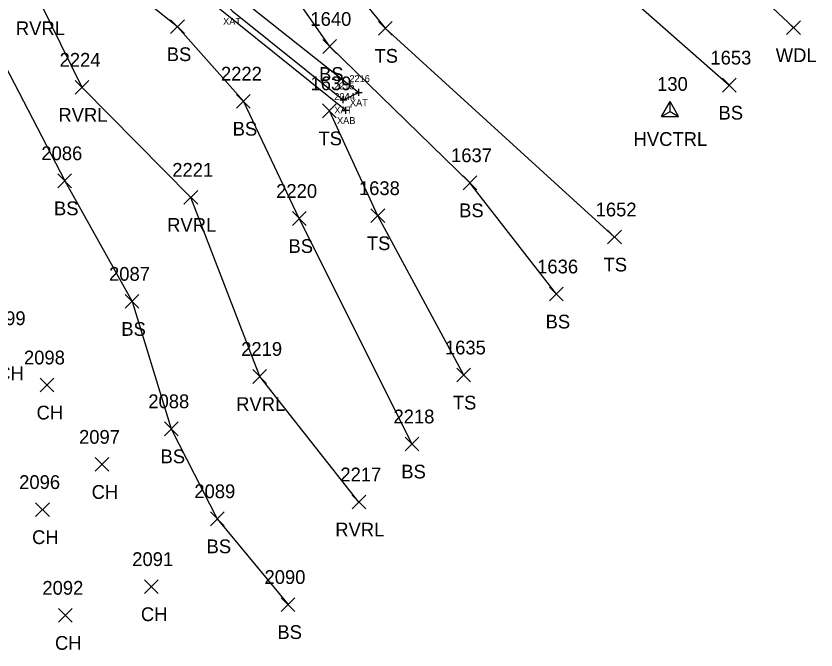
# Model space of a CAD drawing. Extents: x 1647133 to 1649138, y 411736 to 414924.
# Drawn here: x 1648998.1 to 1649114.4, y 412087.9 to 412180 of the extents above; entities that cross this region are included whole.
import ezdxf

# ---------------------------------------------------------------- set-up
doc = ezdxf.new("R2010")
doc.units = 0
for name, color, linetype in [('B_A', 7, 'Continuous'), ('B_I', 7, 'Continuous'), ('B_TIC', 7, 'Continuous'), ('BSUBM', 7, 'Continuous'), ('C_A', 7, 'Continuous'), ('C_I', 7, 'Continuous'), ('CPSM', 7, 'Continuous'), ('L_A', 7, 'Continuous'), ('L_I', 7, 'Continuous'), ('L_TIC', 7, 'Continuous'), ('LAWA', 7, 'Continuous'), ('LAWE', 7, 'Continuous'), ('LELB', 7, 'Continuous')]:
    doc.layers.add(name, color=color, linetype=linetype)

msp = doc.modelspace()

# ---------------------------------------------------------------- linework, layer by layer
at = {"layer": 'B_TIC'}
for p, q in [((1649047.93, 412168.89), (1649048, 412168.89)), ((1649047.93, 412168.89), (1649048, 412168.89)), ((1649045.66, 412167.83), (1649045.74, 412167.83)), ((1649046.03, 412166.3), (1649046.11, 412166.3))]:
    msp.add_line(p, q, dxfattribs=at)
for points in [[(1649047.42, 412168.89), (1649048.42, 412168.89)], [(1649047.42, 412168.89), (1649048.42, 412168.89)], [(1649047.92, 412168.39), (1649047.92, 412169.39)], [(1649047.92, 412168.39), (1649047.92, 412169.39)], [(1649045.16, 412167.83), (1649046.16, 412167.83)], [(1649045.66, 412167.33), (1649045.66, 412168.33)], [(1649045.53, 412166.3), (1649046.53, 412166.3)], [(1649046.03, 412165.8), (1649046.03, 412166.8)]]:
    msp.add_lwpolyline(points, dxfattribs=at)
at = {"layer": 'BSUBM'}
for points in [[(1648980.21, 412272.22), (1648969.68, 412271.32), (1648969.26, 412266.42), (1648968.93, 412254.38), (1648969.05, 412251.5), (1648969.53, 412251.26), (1648969.79, 412227.7), (1648987.09, 412207.48), (1648990.12, 412205.51), (1649004.16, 412198.22), (1649004.66, 412197.94), (1649016.35, 412193.1), (1649025.31, 412183.01), (1649046.03, 412166.3)], [(1648988.03, 412209.13), (1648991.51, 412213.01), (1648996.39, 412206.99), (1649003.26, 412202.8), (1649010.46, 412199.77), (1649020.04, 412194.1), (1649031.36, 412182.02), (1649047.92, 412168.89)], [(1648988.03, 412209.13), (1648994.26, 412203.89), (1649001.04, 412200.28), (1649007.86, 412197.37), (1649018.25, 412192.59), (1649029.49, 412180.72), (1649045.66, 412167.83), (1649047.92, 412168.89)]]:
    msp.add_lwpolyline(points, dxfattribs=at)
at = {"layer": 'CPSM'}
for p, q in [((1649091.92, 412165.4), (1649093.17, 412167.56)), ((1649094.42, 412165.4), (1649093.17, 412167.56)), ((1649093.17, 412166.12), (1649093.17, 412167.56)), ((1649091.92, 412165.4), (1649093.17, 412166.12)), ((1649091.92, 412165.4), (1649094.42, 412165.4)), ((1649093.17, 412166.12), (1649093.17, 412166.12)), ((1649093.17, 412166.12), (1649094.42, 412165.4))]:
    msp.add_line(p, q, dxfattribs=at)
at = {"layer": 'L_TIC'}
for points in [[(1649020.56, 412177.44), (1649022.56, 412179.44)], [(1649022.56, 412177.44), (1649020.56, 412179.44)], [(1649050.79, 412177.2), (1649052.79, 412179.2)], [(1649052.79, 412177.2), (1649050.79, 412179.2)], [(1649110.12, 412177.3), (1649112.12, 412179.3)], [(1649112.12, 412177.3), (1649110.12, 412179.3)], [(1649042.7, 412174.56), (1649044.7, 412176.56)], [(1649044.7, 412174.56), (1649042.7, 412176.56)], [(1649100.78, 412168.94), (1649102.78, 412170.94)], [(1649102.78, 412168.94), (1649100.78, 412170.94)], [(1649006.68, 412168.63), (1649008.68, 412170.63)], [(1649008.68, 412168.63), (1649006.68, 412170.63)], [(1649030.14, 412166.61), (1649032.14, 412168.61)], [(1649032.14, 412166.61), (1649030.14, 412168.61)], [(1649042.64, 412165.21), (1649044.64, 412167.21)], [(1649044.64, 412165.21), (1649042.64, 412167.21)], [(1649004.16, 412155.05), (1649006.16, 412157.05)], [(1649006.16, 412155.05), (1649004.16, 412157.05)], [(1649063.07, 412154.76), (1649065.07, 412156.76)], [(1649065.07, 412154.76), (1649063.07, 412156.76)], [(1649022.5, 412152.64), (1649024.5, 412154.64)], [(1649024.5, 412152.64), (1649022.5, 412154.64)], [(1649038.26, 412149.57), (1649040.26, 412151.57)], [(1649040.26, 412149.57), (1649038.26, 412151.57)], [(1649049.69, 412149.98), (1649051.69, 412151.98)], [(1649051.69, 412149.98), (1649049.69, 412151.98)], [(1649084.09, 412146.88), (1649086.09, 412148.88)], [(1649086.09, 412146.88), (1649084.09, 412148.88)], [(1649013.95, 412137.53), (1649015.95, 412139.53)], [(1649015.95, 412137.53), (1649013.95, 412139.53)], [(1649075.64, 412138.6), (1649077.64, 412140.6)], [(1649077.64, 412138.6), (1649075.64, 412140.6)], [(1649032.52, 412126.62), (1649034.52, 412128.62)], [(1649034.52, 412126.62), (1649032.52, 412128.62)], [(1649062.18, 412126.83), (1649064.18, 412128.83)], [(1649064.18, 412126.83), (1649062.18, 412128.83)], [(1649001.58, 412125.38), (1649003.58, 412127.38)], [(1649003.58, 412125.38), (1649001.58, 412127.38)], [(1649019.66, 412119.02), (1649021.66, 412121.02)], [(1649021.66, 412119.02), (1649019.66, 412121.02)], [(1649054.66, 412116.81), (1649056.66, 412118.81)], [(1649056.66, 412116.81), (1649054.66, 412118.81)], [(1649009.59, 412113.85), (1649011.59, 412115.85)], [(1649011.59, 412113.85), (1649009.59, 412115.85)], [(1649000.94, 412107.28), (1649002.94, 412109.28)], [(1649002.94, 412107.28), (1649000.94, 412109.28)], [(1649046.94, 412108.39), (1649048.94, 412110.39)], [(1649048.94, 412108.39), (1649046.94, 412110.39)], [(1649026.35, 412105.95), (1649028.35, 412107.95)], [(1649028.35, 412105.95), (1649026.35, 412107.95)], [(1649016.75, 412096.09), (1649018.75, 412098.09)], [(1649018.75, 412096.09), (1649016.75, 412098.09)], [(1649036.64, 412093.49), (1649038.64, 412095.49)], [(1649038.64, 412093.49), (1649036.64, 412095.49)], [(1649004.26, 412091.92), (1649006.26, 412093.92)], [(1649006.26, 412091.92), (1649004.26, 412093.92)]]:
    msp.add_lwpolyline(points, dxfattribs=at)
at = {"layer": 'LAWA'}
msp.add_lwpolyline([(1649111.12, 412178.3), (1649089.04, 412199.03), (1649075.25, 412213.99), (1649058.93, 412228.31), (1649052.09, 412230.86), (1649036.04, 412232.41), (1649032.16, 412233.29), (1649023.71, 412232.35), (1649011.83, 412226.16), (1649003.25, 412219.94), (1648994.7, 412211.05)], dxfattribs=at)
at = {"layer": 'LAWE'}
msp.add_lwpolyline([(1649047.94, 412109.39), (1649033.52, 412127.62), (1649023.5, 412153.64), (1649007.68, 412169.63), (1649001.51, 412182.21), (1649004.61, 412194.85)], dxfattribs=at)
at = {"layer": 'LELB'}
for points in [[(1648910.34, 412307.48), (1648923.4, 412285.73), (1648930.01, 412277.07), (1648939.66, 412266.79), (1648945.95, 412259.16), (1648943.1, 412258.5), (1648935.16, 412254.46), (1648928.5, 412254.28), (1648924.41, 412254.2), (1648925.5, 412246.05), (1648929.64, 412242.7), (1648937.31, 412237.26), (1648939.74, 412232.88), (1648942.09, 412231.58), (1648961.5, 412231.41), (1648963.58, 412219.2), (1648985.51, 412194.57), (1648993.76, 412177.98), (1649005.16, 412156.05), (1649014.95, 412138.53), (1649020.66, 412120.02), (1649027.35, 412106.95), (1649037.64, 412094.49)], [(1649076.64, 412139.6), (1649064.07, 412155.76), (1649043.7, 412175.56), (1649025.51, 412201.61), (1649004.57, 412203.92), (1649026.54, 412214.26), (1649035.27, 412210.48), (1649038.43, 412209.72), (1649056.28, 412213.62), (1649076.03, 412192.59), (1649101.78, 412169.94)], [(1649025.51, 412201.61), (1649041.12, 412191.27), (1649051.79, 412178.2), (1649085.09, 412147.88)], [(1649055.66, 412117.81), (1649039.26, 412150.57), (1649031.14, 412167.61), (1649021.56, 412178.44), (1649012.39, 412185.8), (1649004.61, 412194.85)], [(1649063.18, 412127.83), (1649050.69, 412150.98), (1649043.64, 412166.21)]]:
    msp.add_lwpolyline(points, dxfattribs=at)

# ---------------------------------------------------------------- texts
at = {"layer": 'B_A'}
for s, p in [('XAT', (1649028.19, 412178.72)), ('XAT', (1649046.63, 412166.89)), ('XAT', (1649046.63, 412166.89)), ('XAT', (1649044.36, 412165.83)), ('XAB', (1649044.75, 412164.3))]:
    msp.add_text(s, height=1, dxfattribs=at).set_placement(p)
at = {"layer": 'B_I'}
for s, p in [('2216', (1649046.55, 412170.39)), ('2216', (1649046.55, 412170.39)), ('2215', (1649044.31, 412169.33)), ('2044', (1649044.36, 412167.8))]:
    msp.add_text(s, height=1, dxfattribs=at).set_placement(p)
at = {"layer": 'C_A'}
msp.add_text('HVCTRL', height=2, dxfattribs=at).set_placement((1649087.87, 412161.12))
at = {"layer": 'C_I'}
msp.add_text('130', height=2, dxfattribs=at).set_placement((1649091.29, 412169.12))
at = {"layer": 'L_A'}
for s, p in [('RVRL', (1648998.07, 412177.21)), ('BS', (1649020, 412173.44)), ('TS', (1649050.2, 412173.2)), ('WDL', (1649108.54, 412173.3)), ('BS', (1649042.14, 412170.56)), ('RVRL', (1649004.25, 412164.63)), ('BS', (1649100.22, 412164.94)), ('BS', (1649029.58, 412162.61)), ('TS', (1649042.05, 412161.21)), ('BS', (1649003.6, 412151.05)), ('BS', (1649062.51, 412150.76)), ('RVRL', (1649020.06, 412148.64)), ('TS', (1649049.09, 412145.98)), ('BS', (1649037.7, 412145.57)), ('TS', (1649083.5, 412142.88)), ('BS', (1649075.08, 412134.6)), ('BS', (1649013.39, 412133.53)), ('CH', (1648995.36, 412127.09)), ('RVRL', (1649030.09, 412122.62)), ('TS', (1649061.59, 412122.83)), ('CH', (1649001.07, 412121.38)), ('BS', (1649019.1, 412115.02)), ('BS', (1649054.1, 412112.81)), ('CH', (1649009.08, 412109.85)), ('RVRL', (1649044.5, 412104.39)), ('CH', (1649000.42, 412103.28)), ('BS', (1649025.79, 412101.95)), ('CH', (1649016.24, 412092.09)), ('BS', (1649036.08, 412089.49)), ('CH', (1649003.75, 412087.92))]:
    msp.add_text(s, height=2, dxfattribs=at).set_placement(p)
at = {"layer": 'L_I'}
for s, p in [('1640', (1649040.88, 412178.56)), ('2224', (1649004.42, 412172.63)), ('1653', (1649099.04, 412172.94)), ('2222', (1649027.88, 412170.61)), ('1639', (1649040.9, 412169.21)), ('2086', (1649001.77, 412159.05)), ('1637', (1649061.33, 412158.76)), ('2221', (1649020.8, 412156.64)), ('1638', (1649047.94, 412153.98)), ('2220', (1649035.91, 412153.57)), ('1652', (1649082.35, 412150.88)), ('1636', (1649073.85, 412142.6)), ('2087', (1649011.61, 412141.53)), ('2099', (1648993.53, 412135.09)), ('2219', (1649030.82, 412130.62)), ('1635', (1649060.44, 412130.83)), ('2098', (1648999.24, 412129.38)), ('2088', (1649017.32, 412123.02)), ('2218', (1649052.96, 412120.81)), ('2097', (1649007.25, 412117.85)), ('2217', (1649045.24, 412112.39)), ('2096', (1648998.54, 412111.28)), ('2089', (1649024.01, 412109.95)), ('2091', (1649014.98, 412100.09)), ('2090', (1649034.21, 412097.49)), ('2092', (1649001.92, 412095.92))]:
    msp.add_text(s, height=2, dxfattribs=at).set_placement(p)

doc.saveas('drawing.dxf')
